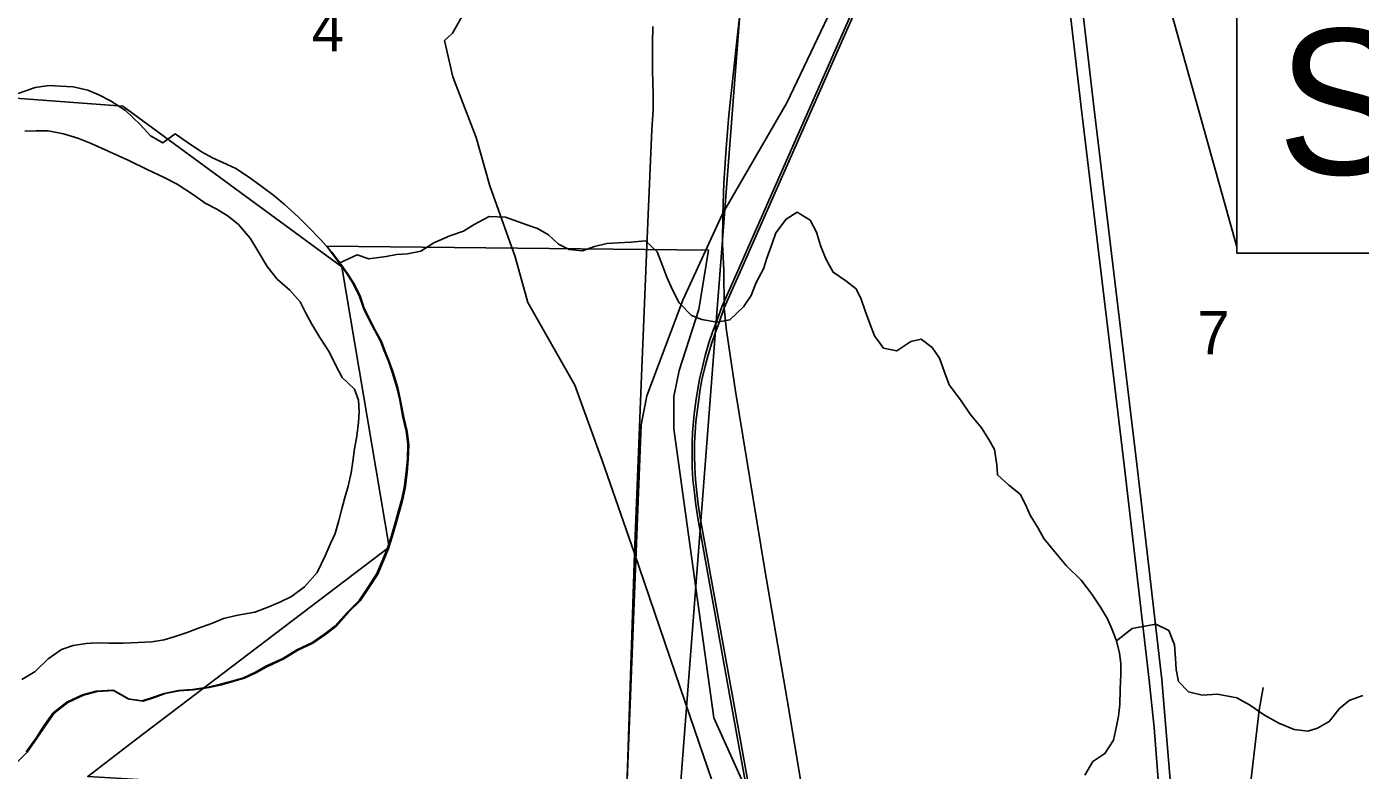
# Model space of a CAD drawing. Extents: x 0 to 34, y 0 to 22.
# Drawn here: x 4.895 to 6.181, y 16.514 to 17.231 of the extents above; entities that cross this region are included whole.
import ezdxf

# ---------------------------------------------------------------- set-up
doc = ezdxf.new("R2010")
doc.units = 0
for name, color, linetype in [('GM_X_Corporation', 7, 'Continuous'), ('GM_X_Major_River', 7, 'Continuous'), ('GM_X_Minor_River', 7, 'Continuous'), ('GM_X_Rail_Line', 7, 'Continuous'), ('GM_X_Section_Text', 7, 'Continuous'), ('GM_X_State_Route', 7, 'Continuous'), ('GM_X_Township_Road', 7, 'Continuous'), ('GM_X_US_Route', 7, 'Continuous'), ('SH_Data', 7, 'Continuous'), ('SH_Text', 7, 'Continuous')]:
    doc.layers.add(name, color=color, linetype=linetype)

msp = doc.modelspace()

# ---------------------------------------------------------------- linework, layer by layer
at = {"layer": 'GM_X_Corporation'}
for points in [[(4.5805, 17.5547), (5.601, 17.4809), (5.5235, 16.4744), (4.954, 16.5082), (5.0002, 16.5433), (5.2448, 16.7292), (5.1991, 16.9994), (4.9878, 17.1542), (4.7159, 17.1745), (4.6324, 17.2045), (4.5566, 17.2317), (4.5614, 17.2965), (4.5617, 17.3002)], [(5.601, 17.4809), (6.5737, 17.4057), (6.463, 16.4089), (5.5235, 16.4744)]]:
    msp.add_lwpolyline(points, close=True, dxfattribs=at)
for points in [[(5.5684, 16.4678), (5.5349, 16.5657), (5.4809, 16.7239), (5.45, 16.8125), (5.4237, 16.8852), (5.3785, 16.9648), (5.366, 17.0089), (5.3416, 17.0774), (5.3284, 17.1238), (5.3061, 17.1824), (5.2981, 17.2174), (5.3056, 17.2244), (5.3162, 17.2432)], [(5.3162, 17.2432), (5.3056, 17.2244), (5.2981, 17.2174), (5.3061, 17.1824), (5.3284, 17.1238), (5.3416, 17.0774), (5.366, 17.0089), (5.3785, 16.9648), (5.4237, 16.8852), (5.45, 16.8125), (5.4809, 16.7239), (5.5349, 16.5657), (5.5684, 16.4678)], [(5.6025, 16.4655), (5.5578, 16.5645), (5.519, 16.8431), (5.519, 16.8743), (5.5242, 16.8993), (5.5432, 16.9583), (5.5527, 17.0153), (5.1845, 17.0193), (5.1961, 17.0036), (5.2032, 16.9937), (5.2093, 16.9842), (5.2157, 16.9717), (5.2198, 16.9595), (5.2251, 16.9489), (5.2307, 16.9379), (5.2364, 16.9277), (5.2398, 16.9182), (5.2439, 16.9083), (5.2477, 16.8977), (5.2522, 16.8829), (5.2548, 16.8708), (5.2578, 16.8545), (5.2612, 16.8408), (5.2626, 16.8279), (5.2622, 16.8143), (5.2611, 16.8014), (5.2591, 16.7862), (5.2565, 16.7745), (5.2538, 16.7642), (5.2504, 16.7525), (5.2465, 16.7392), (5.2431, 16.7282), (5.2385, 16.7172), (5.2328, 16.7036), (5.2241, 16.6903), (5.2157, 16.6778), (5.2044, 16.6665), (5.1922, 16.6528), (5.1827, 16.6456), (5.1702, 16.6369), (5.1558, 16.6301), (5.1422, 16.6218), (5.1259, 16.6143), (5.1157, 16.6086), (5.1043, 16.6033), (5.0929, 16.5999), (5.0819, 16.5969), (5.0702, 16.5942), (5.0551, 16.592), (5.0414, 16.5909), (5.0278, 16.5882), (5.0176, 16.5845), (5.0066, 16.5811), (4.993, 16.583), (4.9782, 16.5913), (4.9623, 16.5902), (4.9491, 16.5868), (4.9339, 16.5796), (4.9206, 16.5694), (4.9123, 16.5577), (4.9039, 16.5448), (4.8948, 16.5319)]]:
    msp.add_lwpolyline(points, dxfattribs=at)
at = {"layer": 'GM_X_Major_River'}
for points in [[(5.0287, 16.5879), (5.0423, 16.5905), (5.056, 16.5916), (5.0711, 16.5939), (5.0829, 16.5965), (5.0938, 16.5996), (5.1052, 16.6029), (5.1166, 16.6082), (5.1268, 16.6139), (5.1431, 16.6215), (5.1567, 16.6298), (5.1711, 16.6366), (5.1836, 16.6453), (5.1931, 16.6525), (5.2053, 16.6661), (5.2167, 16.6775), (5.225, 16.69), (5.2337, 16.7032), (5.2395, 16.7169), (5.244, 16.7279), (5.2475, 16.7389), (5.2513, 16.7521), (5.2547, 16.7639), (5.2574, 16.7741), (5.2601, 16.7859), (5.262, 16.801), (5.2631, 16.8139), (5.2636, 16.8276), (5.2621, 16.8405), (5.2587, 16.8541), (5.2557, 16.8704), (5.2531, 16.8826), (5.2486, 16.8974), (5.2448, 16.908), (5.2407, 16.9178), (5.2373, 16.9273), (5.2316, 16.9376), (5.226, 16.9486), (5.2207, 16.9592), (5.2166, 16.9713), (5.2102, 16.9839), (5.2041, 16.9933), (5.197, 17.0032), (5.1894, 17.0135), (5.1789, 17.0252), (5.1664, 17.0381), (5.157, 17.0476), (5.1434, 17.0598), (5.1335, 17.0681), (5.1222, 17.0765), (5.109, 17.086), (5.0969, 17.094), (5.0844, 17.0997), (5.0742, 17.1043), (5.0636, 17.11), (5.05, 17.1195), (5.0383, 17.1274), (5.0265, 17.1187), (5.0144, 17.1256), (5.0046, 17.1366), (4.9903, 17.1499), (4.9759, 17.1594), (4.9646, 17.1651), (4.954, 17.1696), (4.94, 17.1727), (4.9279, 17.1735), (4.9169, 17.1739), (4.9033, 17.172), (4.887, 17.1663)], [(4.8933, 17.1299), (4.9043, 17.1303), (4.916, 17.1303), (4.9308, 17.1276), (4.9444, 17.1234), (4.9573, 17.1181), (4.9739, 17.1108), (4.9936, 17.1017), (5.0121, 17.0926), (5.0272, 17.0857), (5.0404, 17.0789), (5.0559, 17.0686), (5.0673, 17.0607), (5.0786, 17.055), (5.0896, 17.0481), (5.0994, 17.0401), (5.1107, 17.0269), (5.1179, 17.0147), (5.1269, 16.9995), (5.1368, 16.9874), (5.1488, 16.9767), (5.159, 16.9654), (5.1643, 16.9547), (5.17, 16.9441), (5.1779, 16.9312), (5.1869, 16.9175), (5.1926, 16.9054), (5.1994, 16.8925), (5.2114, 16.8815), (5.2152, 16.8709), (5.2159, 16.8595), (5.2152, 16.8496), (5.2136, 16.836), (5.2113, 16.8239), (5.2098, 16.8117), (5.2079, 16.8007), (5.2052, 16.7878), (5.2017, 16.7757), (5.1991, 16.7659), (5.196, 16.7549), (5.1926, 16.7424), (5.188, 16.7325), (5.1831, 16.7208), (5.1751, 16.7048), (5.1629, 16.6908), (5.1504, 16.6814), (5.1394, 16.6761), (5.1269, 16.6708), (5.1152, 16.6663), (5.0989, 16.6636), (5.0849, 16.6602), (5.0743, 16.6557), (5.0599, 16.6508), (5.05, 16.647), (5.0383, 16.6429), (5.0277, 16.6398), (5.016, 16.638), (5.0027, 16.6372), (4.9883, 16.6365), (4.9743, 16.6365), (4.9622, 16.6369)], [(4.9622, 16.6369), (4.9524, 16.6362), (4.9399, 16.6343), (4.9289, 16.6305), (4.916, 16.6214), (4.9035, 16.6093), (4.8906, 16.6017)], [(4.884, 16.5199), (4.8957, 16.5316), (4.9048, 16.5445), (4.9132, 16.5573), (4.9216, 16.5691), (4.9348, 16.5793), (4.95, 16.5865), (4.9632, 16.5899), (4.9791, 16.591), (4.9939, 16.5826), (5.0075, 16.5807), (5.0185, 16.5841), (5.0287, 16.5879)]]:
    msp.add_lwpolyline(points, dxfattribs=at)
at = {"layer": 'GM_X_Minor_River'}
for points in [[(5.197, 17.0032), (5.2137, 17.0109), (5.225, 17.0071), (5.2417, 17.0093), (5.2519, 17.0112), (5.2625, 17.0119), (5.2751, 17.0145), (5.2876, 17.0224), (5.3032, 17.0292), (5.3164, 17.0337), (5.3267, 17.0401), (5.3411, 17.0477), (5.3567, 17.0472), (5.3775, 17.0396), (5.3877, 17.0361), (5.3982, 17.03), (5.408, 17.0212), (5.4183, 17.0159), (5.4311, 17.0147), (5.4425, 17.0188), (5.4546, 17.0218), (5.4656, 17.0225), (5.4778, 17.0232), (5.4918, 17.0243), (5.5031, 17.0137), (5.5076, 17.0023), (5.5124, 16.9893), (5.5177, 16.9772), (5.5244, 16.9646), (5.5361, 16.9525), (5.546, 16.9486), (5.5607, 16.9459), (5.5732, 16.9481), (5.5862, 16.9606), (5.5938, 16.9716), (5.5984, 16.9841), (5.6057, 16.9973), (5.6087, 17.0076), (5.6141, 17.0216), (5.6176, 17.0322), (5.6275, 17.0451), (5.6381, 17.0519), (5.6506, 17.0442), (5.6566, 17.0328), (5.6607, 17.0199), (5.6656, 17.007), (5.6727, 16.9941), (5.6851, 16.9857), (5.695, 16.978), (5.6998, 16.9682), (5.7036, 16.9568), (5.7084, 16.9438), (5.7125, 16.9328), (5.7212, 16.921), (5.7341, 16.9183), (5.7477, 16.9274), (5.7576, 16.9296), (5.7682, 16.9216), (5.7753, 16.9113), (5.7798, 16.8988), (5.7847, 16.8855), (5.7956, 16.871), (5.805, 16.8573), (5.8159, 16.844), (5.8227, 16.833), (5.8283, 16.8231), (5.8305, 16.8083), (5.8312, 16.7988), (5.8421, 16.7889), (5.8531, 16.7801), (5.8583, 16.7703), (5.8628, 16.76), (5.8703, 16.7475), (5.876, 16.7376), (5.8877, 16.7231), (5.8974, 16.7113), (5.9118, 16.6972), (5.9223, 16.6839), (5.9306, 16.6713), (5.9373, 16.6599), (5.9415, 16.6504), (5.946, 16.6387), (5.9489, 16.6269), (5.95, 16.617), (5.95, 16.6068), (5.9495, 16.592), (5.9491, 16.5776), (5.9479, 16.5662), (5.9459, 16.5567), (5.9432, 16.543), (5.9348, 16.5302), (5.923, 16.5226), (5.9154, 16.5094)], [(5.946, 16.6387), (5.9612, 16.6507), (5.9733, 16.653), (5.9839, 16.6548), (5.9964, 16.6487), (6.002, 16.635), (6.0027, 16.6217), (6.0034, 16.6111), (6.0056, 16.5997), (6.0154, 16.5898), (6.0287, 16.5864), (6.0434, 16.5874), (6.062, 16.584), (6.0741, 16.5771), (6.0888, 16.5672), (6.1024, 16.5595), (6.1171, 16.5534), (6.1304, 16.5518), (6.1399, 16.5545), (6.1509, 16.5612), (6.1608, 16.5737), (6.1703, 16.5813), (6.1836, 16.5862)]]:
    msp.add_lwpolyline(points, dxfattribs=at)
at = {"layer": 'GM_X_Rail_Line'}
for points in [[(7.3406, 20.9), (7.1679, 20.8267), (6.9443, 20.7584), (6.8957, 20.7301), (6.8223, 20.6784), (6.7693, 20.6363), (6.6967, 20.5618), (6.6506, 20.4948), (6.6233, 20.4356), (6.5795, 20.2572), (6.397, 19.5172), (6.2733, 19.0197), (6.2341, 18.8804), (6.1559, 18.6926), (6.1001, 18.5873), (6.0785, 18.5248), (6.0655, 18.461), (6.0434, 18.3203), (5.9617, 17.9036), (5.9172, 17.7944), (5.7728, 17.4608), (5.628, 17.1574), (5.5662, 17.0504)], [(5.6033, 16.4188), (5.5736, 16.5834), (5.5422, 16.7571), (5.5403, 16.77), (5.539, 16.7816), (5.5376, 16.7942), (5.5369, 16.8059), (5.5367, 16.8176), (5.5368, 16.8299), (5.5372, 16.8397), (5.538, 16.8501), (5.5391, 16.8598), (5.5407, 16.8718), (5.5422, 16.8816), (5.5438, 16.8909), (5.5471, 16.9042), (5.5495, 16.9139), (5.553, 16.9259), (5.5569, 16.9372), (5.5604, 16.9464), (5.5654, 16.9607), (5.5834, 17.0012), (5.6108, 17.0633), (5.8008, 17.4935)], [(5.6057, 16.4193), (5.5759, 16.5838), (5.5446, 16.7575), (5.5427, 16.7703), (5.5414, 16.7818), (5.54, 16.7944), (5.5393, 16.806), (5.5391, 16.8176), (5.5392, 16.8298), (5.5396, 16.8396), (5.5404, 16.8499), (5.5415, 16.8596), (5.5431, 16.8715), (5.5446, 16.8813), (5.5462, 16.8904), (5.5494, 16.9036), (5.5518, 16.9133), (5.5553, 16.9252), (5.5592, 16.9363), (5.5627, 16.9456), (5.5677, 16.9598), (5.5856, 17.0003), (5.613, 17.0623), (5.803, 17.4925)], [(5.6485, 16.4609), (5.6283, 16.582), (5.6067, 16.7092), (5.5786, 16.8793), (5.5695, 16.9402), (5.5677, 16.9598), (5.5675, 16.9963), (5.5661, 17.021), (5.5664, 17.0498), (5.5675, 17.0798), (5.5696, 17.1138), (5.5723, 17.1454), (5.5805, 17.223), (5.5915, 17.3188)], [(5.5662, 17.0504), (5.5279, 16.9673), (5.4932, 16.875), (5.4877, 16.847), (5.4731, 16.4797), (5.4495, 15.8212), (5.4332, 15.3872), (5.4826, 14.849), (5.4878, 14.7927), (5.5273, 14.5888)]]:
    msp.add_lwpolyline(points, dxfattribs=at)
at = {"layer": 'GM_X_State_Route'}
for points in [[(5.4991, 17.1517), (5.4991, 17.1653), (5.4986, 17.1884), (5.4986, 17.2146), (5.4988, 17.231)], [(5.4941, 17.0423), (5.4978, 17.1314), (5.4991, 17.1507), (5.4991, 17.1517)], [(5.4635, 16.2248), (5.469, 16.3755), (5.4733, 16.4775), (5.4811, 16.7234), (5.4879, 16.8939), (5.4941, 17.0423)]]:
    msp.add_lwpolyline(points, dxfattribs=at)
at = {"layer": 'GM_X_Township_Road'}
msp.add_lwpolyline([(6.0643, 16.3168), (6.0648, 16.3291), (6.0675, 16.3563), (6.0683, 16.37), (6.0683, 16.3815), (6.0683, 16.4021), (6.0678, 16.4136), (6.0672, 16.424), (6.067, 16.4347), (6.0675, 16.4416), (6.0692, 16.4511), (6.0834, 16.5721), (6.0872, 16.594)], dxfattribs=at)
at = {"layer": 'GM_X_US_Route'}
for points in [[(6.0524, 15.6089), (6.0451, 15.6305), (6.0388, 15.6521), (6.033, 15.6781), (6.0301, 15.7013), (6.0282, 15.7202), (6.0267, 15.7497), (6.0172, 15.9189), (6.0082, 16.106), (5.9909, 16.4287), (5.9864, 16.5011), (5.9822, 16.5554), (5.9775, 16.6009), (5.9633, 16.723), (5.9533, 16.8083), (5.912, 17.1531), (5.8806, 17.4212)], [(6.0904, 15.6104), (6.0832, 15.6229), (6.0756, 15.637), (6.0678, 15.6534), (6.0618, 15.668), (6.0558, 15.6846), (6.0517, 15.6979), (6.0477, 15.7129), (6.0432, 15.7328), (6.0403, 15.7513), (6.0379, 15.7729), (6.0363, 15.7962), (6.0295, 15.9198), (6.0274, 15.9623), (6.025, 16.0084), (6.0215, 16.076), (6.0192, 16.1198), (6.0032, 16.4296), (5.9977, 16.5049), (5.9898, 16.6017), (5.9756, 16.7239), (5.9656, 16.8091), (5.9242, 17.1539), (5.8929, 17.4221)]]:
    msp.add_lwpolyline(points, dxfattribs=at)
at = {"layer": 'SH_Data'}
for p, q in [((6.0621, 17.0126), (6.0621, 17.4995)), ((7.9543, 17.0126), (6.0621, 17.0126))]:
    msp.add_line(p, q, dxfattribs=at)
msp.add_lwpolyline([(6.0621, 17.4995), (5.8406, 17.8107), (6.0621, 17.0185)], close=True, dxfattribs=at)

# ---------------------------------------------------------------- texts
at = {"layer": 'GM_X_Section_Text'}
for s, p in [('4', (5.1701, 17.2071)), ('7', (6.0238, 16.9148))]:
    msp.add_text(s, height=0.0419, rotation=0, dxfattribs=at).set_placement(p)
at = {"layer": 'SH_Text'}
msp.add_text('STA. 814+10 U.S. 23', height=0.14, dxfattribs=at).set_placement((6.1009, 17.0884))

doc.saveas('drawing.dxf')
